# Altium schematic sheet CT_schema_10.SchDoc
size 388 x 278 mm
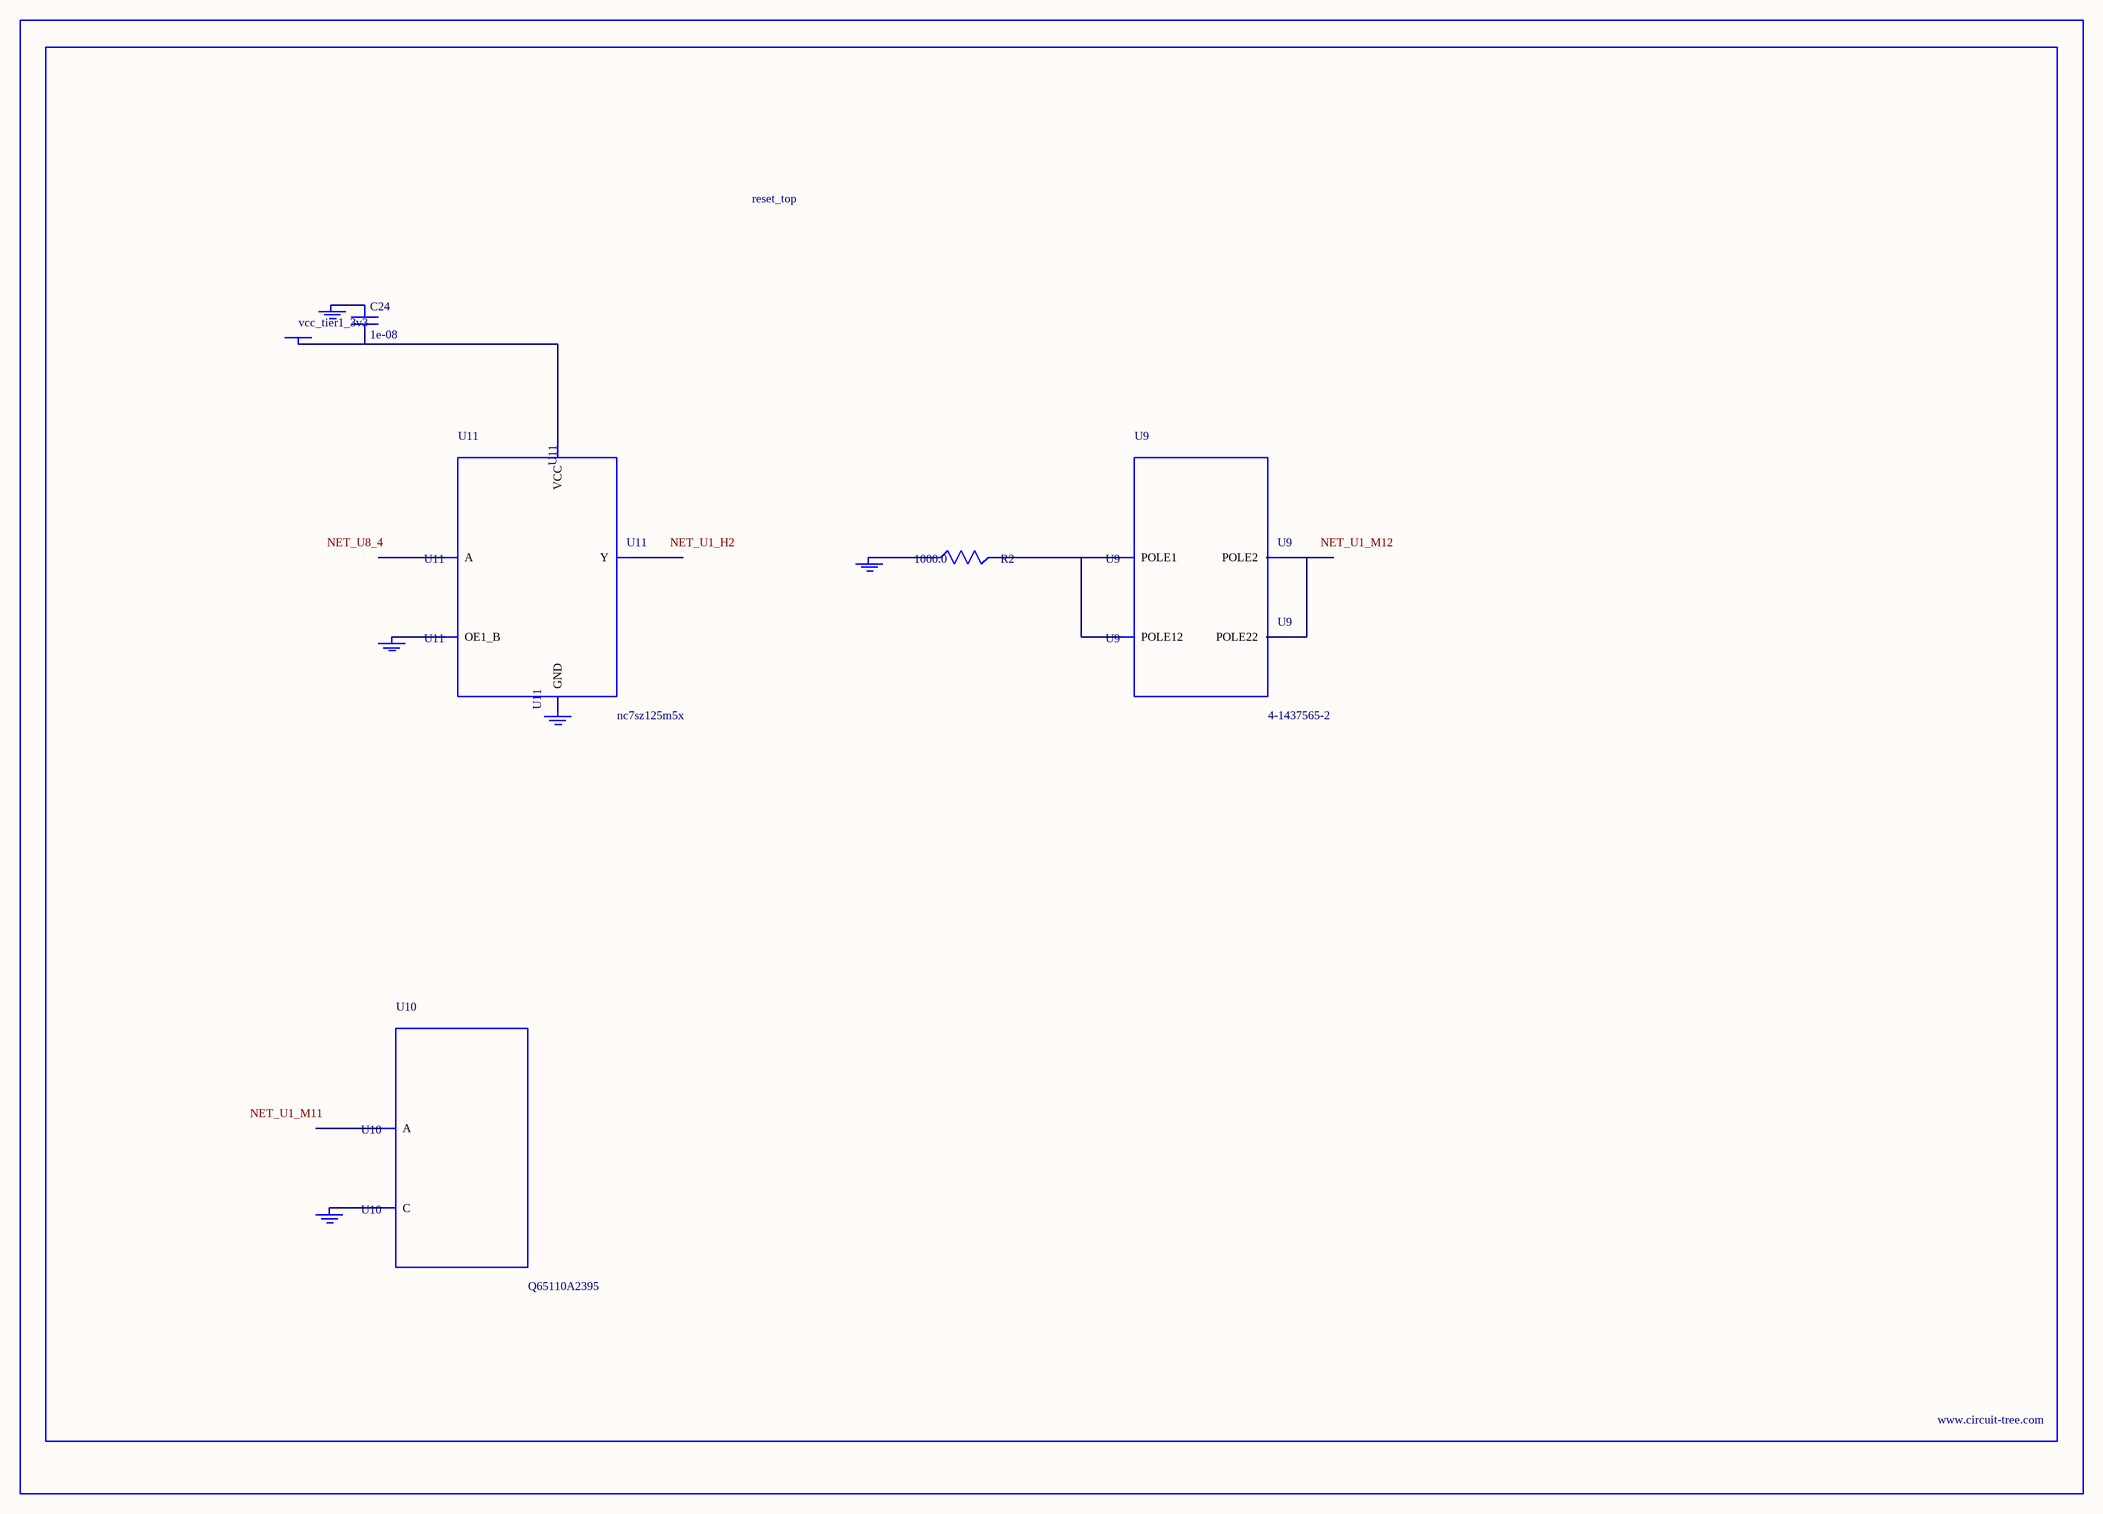
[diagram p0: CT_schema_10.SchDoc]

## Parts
BORDER9  (no value)
C24  1e-08  [C0402]
GND_INSTANCE_9_0  (no value)
GND_INSTANCE_9_1  (no value)
GND_INSTANCE_9_2  (no value)
GND_INSTANCE_9_3  (no value)
GND_INSTANCE_9_4  (no value)
POWER_INSTANCE_9_0  vcc_tier1_3v3
R2  1000.0  [R0603]
U9  4-1437565-2  [SW_4-1437565-2]
U10  Q65110A2395  [LGM67K-G1J2-24-Z]
U11  nc7sz125m5x  [NC7SZ125M5X]

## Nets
NetC24_1: C24.1 GND_INSTANCE_9_2.0(GND)
NetC24_2: C24.2 POWER_INSTANCE_9_0.0(PWR) U11.5(VCC)
NetGND_INSTANCE_9_0_0: GND_INSTANCE_9_0.0(GND) R2.1
NetGND_INSTANCE_9_1_0: GND_INSTANCE_9_1.0(GND) U10.C
NetGND_INSTANCE_9_3_0: GND_INSTANCE_9_3.0(GND) U11.1(OE1_B)
NetGND_INSTANCE_9_4_0: GND_INSTANCE_9_4.0(GND) U11.3(GND)
NetR2_2: R2.2 U9.1(POLE1) U9.2(POLE12)
NetU9_3: U9.3(POLE2) U9.4(POLE22)

Not connected (* = marked no-connect by the designer): U10 A; U11 2(A) 4(Y)

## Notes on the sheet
- Labels drawn without touching a wire or pin: NET_U1_H2, NET_U1_M11, NET_U1_M12, NET_U8_4

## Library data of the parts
BORDER9 = BORDER_PAGE9
C24 = C0402C103K3RAC
GND_INSTANCE_9_0-GND_INSTANCE_9_4 = GND
POWER_INSTANCE_9_0 = PWR
R2 = RC0603JR-071KL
